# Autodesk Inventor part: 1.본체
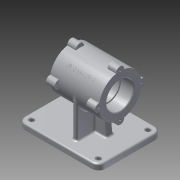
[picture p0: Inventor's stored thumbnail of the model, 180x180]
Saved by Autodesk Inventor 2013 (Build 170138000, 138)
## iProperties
Created: 2015-12
Part Number: 1.본체
Material: 알루미늄 6061
Document SubType Name: 판금
Designer: hana
Density: 2.40731 g/cm^3
Sheet Metal Rule: 기본값
Mass: 1036.86 g
Surface Area: 821.401 cm^2
Volume: 430.713 cm^3
Author: hana
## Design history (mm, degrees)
sketch "스케치1"
  geometry: L1 (-80, 55)-(60, 55); L2 (60, 55)-(60, -55); L3 (60, -55)-(-80, -55); L4 (-80, -55)-(-80, 55); 2 further points
  constraints: 8 end point, 2 parallel, 1 horizontal, 1 horizontal alignment, 1 midpoint, 1 perpendicular
  dimensions: "d0" = 140 distance of L1.start L1.end; "d2" = 110 distance of L3.end L1.start; "d3" = 80 distance from line of L4 point (0, 0)
extrude "돌출1" new body sketch "스케치1" distance "d4" = 10; taper "d5" = 0 deg
node "작업 평면1"
sketch "스케치2"
  geometry: L1 (-42.5, 117)-(42.5, 117); L2 (42.5, 117)-(42.5, 80); L3 (42.5, 80)-(-42.5, 80); L4 (-42.5, 80)-(-42.5, 117); L5 (-80, 0)-(-80, 10) reference; L6 (-80, 10)-(60, 10) reference; L7 (60, 10)-(60, 0) reference; L8 (60, 0)-(-80, 0) reference; 1 further point
  constraints: 8 end point, 2 perpendicular, 1 horizontal, 1 parallel
  dimensions: "d7" = 74 diameter of L1 L3; "d9" = 85 distance of L1.start L1.end; "d10" = 37.5 distance between parallel lines of L4 L5; "d11" = 80 distance from line of L8 L3.end
revolve "회전1" sketch "스케치2" stored, may be unused: angle "d12" = 90 deg
sketch "스케치3"
  geometry: L1 (-80, 0)-(-80, 10) reference; L2 (-80, 10)-(60, 10) reference; L3 (60, 10)-(60, 0) reference; L4 (60, 0)-(-80, 0) reference; L5 (-42.5, 43)-(-42.5, 117) reference; L6 (-42.5, 117)-(42.5, 117) reference; L7 (42.5, 117)-(42.5, 43) reference; L8 (42.5, 43)-(-42.5, 43) reference; L9 (-42.5, 80)-(42.5, 80); L10 (42.5, 103.5)-(20.5, 103.5); L11 (20.5, 103.5)-(20.5, 101); L12 (20.5, 101)-(-20.5, 101); L13 (-20.5, 101)-(-20.5, 103.5); L14 (-20.5, 103.5)-(-42.5, 103.5); L15 (-42.5, 103.5)-(-42.5, 80); L16 (42.5, 103.5)-(42.5, 80); 1 further point
  constraints: 16 end point, 3 parallel, 3 perpendicular, 2 midpoint, 2 point on line, 1 collinear
  dimensions: "d13" = 47 diameter of L14 L9; "d15" = 47 diameter of L10 L9; "d16" = 42 diameter of L12 L9; "d17" = 22 distance of L13.end L14.end; "d18" = 41 distance of L11.end L12.end
revolve "회전2" sketch "스케치3" stored, may be unused: angle "d19" = 90 deg
sketch "스케치4"
  geometry: C1 r 23.5 at (0, 0) reference; C2 r 7 at (-37, 0); C3 r 7 at (0, 37); C4 r 7 at (37, 0); C5 r 7 at (0, -37); 1 further point
  constraints: 4 centre point, 2 horizontal alignment, 2 vertical alignment
  dimensions: "d20" = 37 distance of C1.centre C2.centre; "d21" = 14 diameter of C2; "d22" = 14 diameter of C3; "d23" = 14 diameter of C4; "d24" = 14 diameter of C5; "d25" = 37 distance of C3.centre C1.centre; "d26" = 37 distance of C4.centre C1.centre; "d27" = 37 distance of C1.centre C5.centre
extrude "돌출2" join sketch "스케치4" distance "d28" = 15; taper "d29" = 0 deg
sketch "스케치5"
  geometry: A1 r 7 centre (0, 0) between (-0.662, -6.969) and (-0.662, 6.969) reference; A2 r 7 centre (-37, 37) between (-30.031, 36.338) and (-43.969, 36.338) reference; A3 r 7 centre (-74, 0) between (-73.338, 6.969) and (-73.338, -6.969) reference; A4 r 7 centre (-37, -37) between (-43.969, -36.338) and (-30.031, -36.338) reference; 1 further point
hole "구멍1" sketch "스케치5" at (-74, 0), (-37, -37), (0, 0), (-37, 37) diameter "d30" = 3.242; stored, may be unused: countersink angle "d34" = 90 deg, drill point angle "d36" = 118 deg; dims "d31" = 9, "d32" = 4, "d33" = 2, "d35" = 11
node "작업 평면2"
sketch "스케치6"
  geometry: L1 (-4, 37)-(4, 37); L2 (4, 37)-(4, -37); L3 (4, -37)-(-4, -37); L4 (-4, -37)-(-4, 37); 3 further points
  constraints: 8 end point, 2 midpoint, 2 parallel, 1 horizontal, 1 horizontal alignment, 1 perpendicular, 1 vertical alignment
  dimensions: "d37" = 8 distance of L1.start L1.end; "d39" = 74 distance of L3.end L1.start
extrude "돌출3" join sketch "스케치6" stored distance "d40" = 15; taper "d41" = 0 deg
sketch "스케치7"
  geometry: L1 (42.5, 103.5)-(20.5, 103.5) reference; L2 (20.5, 103.5)-(20.5, 101) reference; L3 (20.5, 101)-(-20.5, 101) reference; L4 (-20.5, 101)-(-20.5, 103.5) reference; L5 (-20.5, 103.5)-(-42.5, 103.5) reference; L6 (-42.5, 103.5)-(-42.5, 115.379) reference; L7 (-42.5, 115.379)-(-31.5, 115.379) reference; L8 (-31.5, 115.379)-(-30.526, 117) reference; L9 (-30.526, 117)-(-31.5, 118.621) reference; L10 (-31.5, 118.621)-(-42.5, 118.621) reference; L11 (-42.5, 118.621)-(-42.5, 124) reference; L12 (-42.5, 124)-(-27.5, 124) reference; L13 (-27.5, 124)-(-27.5, 117) reference; L14 (-27.5, 117)-(27.5, 117) reference; L15 (27.5, 117)-(27.5, 124) reference; L16 (27.5, 124)-(42.5, 124) reference; L17 (42.5, 124)-(42.5, 118.621) reference; L18 (42.5, 118.621)-(31.5, 118.621) reference; L19 (31.5, 118.621)-(30.526, 117) reference; L20 (30.526, 117)-(31.5, 115.379) reference; L21 (31.5, 115.379)-(42.5, 115.379) reference; L22 (42.5, 115.379)-(42.5, 103.5) reference; L23 (-80, 0)-(-80, 10) reference; L24 (-80, 10)-(-4, 10) reference; L25 (-4, 10)-(-4, 43) reference; L26 (-4, 43)-(-27.5, 43) reference; L27 (-27.5, 43)-(-27.5, 36) reference; L28 (-27.5, 36)-(-42.5, 36) reference; L29 (-42.5, 36)-(-42.5, 41.379) reference; L30 (-42.5, 41.379)-(-31.5, 41.379) reference; L31 (-31.5, 41.379)-(-30.526, 43) reference; L32 (-30.526, 43)-(-31.5, 44.621) reference; L33 (-31.5, 44.621)-(-42.5, 44.621) reference; L34 (-42.5, 44.621)-(-42.5, 56.5) reference; L35 (-42.5, 56.5)-(-20.5, 56.5) reference; L36 (-20.5, 56.5)-(-20.5, 59) reference; L37 (-20.5, 59)-(20.5, 59) reference; L38 (20.5, 59)-(20.5, 56.5) reference; L39 (20.5, 56.5)-(42.5, 56.5) reference; L40 (42.5, 56.5)-(42.5, 44.621) reference; L41 (42.5, 44.621)-(31.5, 44.621) reference; L42 (31.5, 44.621)-(30.526, 43) reference; L43 (30.526, 43)-(31.5, 41.379) reference; L44 (31.5, 41.379)-(42.5, 41.379) reference; L45 (42.5, 41.379)-(42.5, 36) reference; L46 (42.5, 36)-(27.5, 36) reference; L47 (27.5, 36)-(27.5, 43) reference; L48 (27.5, 43)-(4, 43) reference; L49 (4, 43)-(4, 10) reference; L50 (4, 10)-(60, 10) reference; L51 (60, 10)-(60, 0) reference; L52 (60, 0)-(-80, 0) reference; L53 (-20.948, 43)-(-25, 10); L54 (20.948, 43)-(25, 10); 1 further point
  constraints: 4 end point, 4 point on line
  dimensions: "d42" = 97 deg angle of L53 L24; "d44" = 25 horizontal distance of point (0, 0) L53.end; "d45" = 25 horizontal distance of L54.end point (0, 0); "d46" = 97 deg angle of L50 L54
  node "절단 모서리 투영3"
feature "리브1" dims "d47" = 1, "d48" = 12, "d49" = 0, "d50" = 0, "d51" = 1, "d52" = 1
feature "리브2" dims "d53" = 1, "d54" = 12, "d55" = 0, "d56" = 0, "d57" = 1, "d58" = 1
sketch "스케치8"
  geometry: L1 (80, -55)-(80, 55) reference; L2 (80, 55)-(-60, 55) reference; L3 (-60, 55)-(-60, -55) reference; L4 (-60, -55)-(80, -55) reference; C1 r 4 at (-48, 43); C2 r 4 at (68, 43); C3 r 4 at (68, -43); C4 r 4 at (-48, -43); 1 further point
  constraints: 4 centre point
  dimensions: "d59" = 8 diameter of C1; "d61" = 8 diameter of C2; "d62" = 8 diameter of C3; "d63" = 8 diameter of C4; "d64" = 12 distance from line of L3 C1.centre; "d65" = 12 distance from line of L2 C1.centre; "d66" = 12 distance from line of L4 C4.centre; "d67" = 12 distance from line of L3 C4.centre; "d68" = 12 distance from line of L1 C3.centre; "d69" = 12 distance from line of L4 C3.centre; "d70" = 12 distance from line of L2 C2.centre; "d71" = 12 distance from line of L1 C2.centre
extrude "돌출4" cut sketch "스케치8" stored distance "d72" = 15; taper "d73" = 0 deg
fillet "모깎기1" dims "d74" = 12
fillet "모깎기2" dims "d75" = 3
fillet "모깎기3" dims "d76" = 3
fillet "모깎기4" dims "d77" = 3
chamfer "모따기1" distance "d78" = 1; stored, may be unused: second distance "d79" = 2, angle "d80" = 45 deg
fillet "모깎기5" dims "d81" = 0.3
node "작업 평면5"
  node "작업 평면4"
node "작업 평면7"
  node "작업 평면6"
sketch "스케치12"
  geometry: L1 (-42.5, 0)-(42.5, 0) reference; L2 (-42.5, 30.622)-(-42.5, 37) reference; 3 further points
  constraints: 1 coincident, 1 midpoint, 1 other
  dimensions: "d87" = 42.5 distance from line of point (0, 0) L2
feature "엠보싱2" sketch "스케치12" dims "d0" = 140, "d2" = 110, "d3" = 80, "d13" = 47, "d15" = 47, "d16" = 42, "d17" = 22, "d18" = 41, "d88" = 0.5, "d89" = 0
chamfer "모따기2" distance "d90" = 1; stored, may be unused: second distance "d91" = 2, angle "d92" = 45 deg
node "솔리드1"
mirror "대칭1"
node "작업 평면3"
node "작업축1"
node "작업축2"
node "절단 모서리 투영1"
node "절단 모서리 투영2"
node "절단 모서리 투영6"
other parameters: "d6" = 90 deg, "d82" = -45 deg, "d86" = 45 deg, "K계수" = 4.4, "BendRadius" = 0.5 (derived), "BendReliefWidth" = 0.5 (derived), "BendReliefDepth" = 0.25 (derived), "CornerReliefSize" = 2 (derived), "SeamGap" = 0.01, "MinimumRemnant" = 1 (derived), "TransitionRadius" = 0.5 (= BendRadius)
